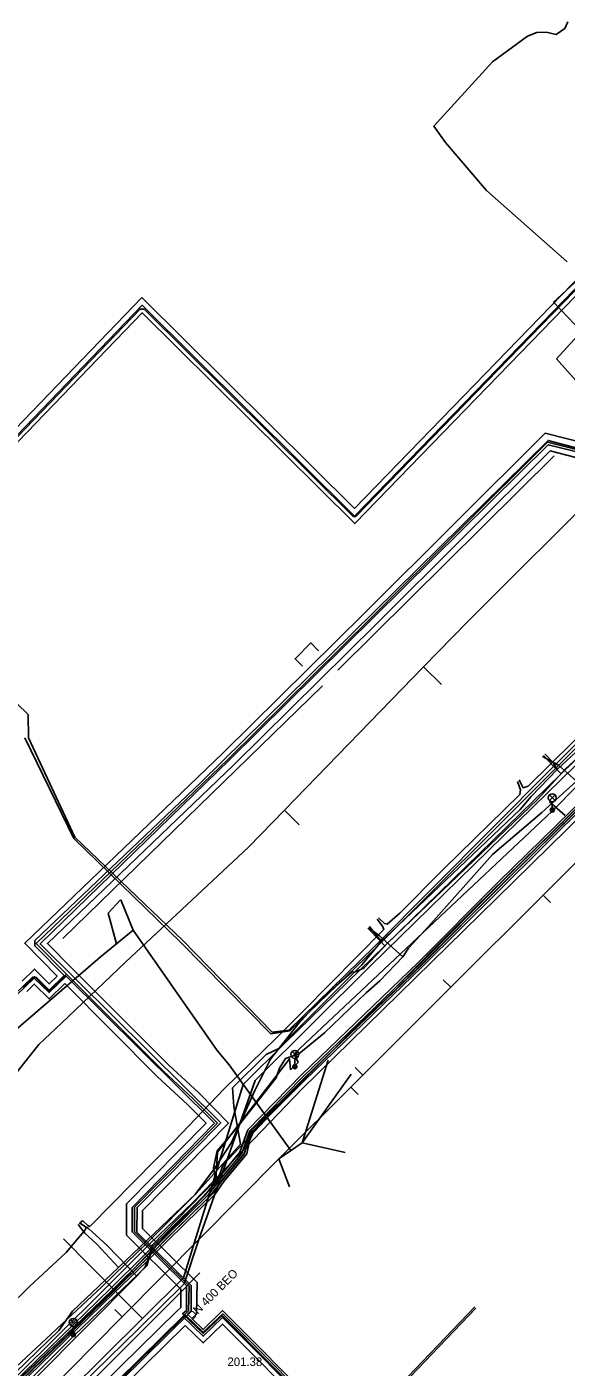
# Model space of a CAD drawing. Extents: x -598932 to -598196, y -1162210 to -1161504.
# Drawn here: x -598778.2 to -598727.6, y -1161725.1 to -1161599.2 of the extents above; entities that cross this region are included whole.
import ezdxf

# ---------------------------------------------------------------- set-up
doc = ezdxf.new("R2010")
doc.units = 0
for name, color, linetype in [('Vrstva 1', 7, 'Continuous'), ('Vrstva 12', 7, 'Continuous'), ('Vrstva 13', 7, 'Continuous'), ('Vrstva 14', 7, 'Continuous'), ('Vrstva 16', 7, 'Continuous'), ('Vrstva 25', 7, 'Continuous'), ('Vrstva 26', 7, 'Continuous'), ('Vrstva 29', 7, 'Continuous'), ('Vrstva 30', 7, 'Continuous'), ('Vrstva 33', 7, 'Continuous'), ('Vrstva 42', 7, 'Continuous'), ('Vrstva 44', 7, 'Continuous'), ('Vrstva 55', 7, 'Continuous'), ('Vrstva 58', 7, 'Continuous'), ('Vrstva 9', 7, 'Continuous')]:
    doc.layers.add(name, color=color, linetype=linetype)

msp = doc.modelspace()

# ---------------------------------------------------------------- linework, layer by layer
at = {"layer": 'Vrstva 1'}
for p, q in [((-598769.442, -1161681.198), (-598770.611, -1161682.438)), ((-598768.26, -1161684.05), (-598769.42, -1161681.2)), ((-598769.81, -1161685.315), (-598770.611, -1161682.438)), ((-598759.23, -1161696.7), (-598753.43, -1161704.739)), ((-598749.925, -1161696.249), (-598752.364, -1161704.006)), ((-598747.77, -1161697.55), (-598752.364, -1161704.006)), ((-598754.576, -1161705.527), (-598752.364, -1161704.006))]:
    msp.add_line(p, q, dxfattribs=at)
msp.add_lwpolyline([(-598810.55, -1161722.32), (-598793.435, -1161705.545), (-598771.36, -1161686.58), (-598768.26, -1161684.05), (-598760.37, -1161695.35), (-598759.23, -1161696.7)], dxfattribs=at)
at = {"layer": 'Vrstva 12'}
for p, q in [((-598769.62, -1161715.73), (-598771.68, -1161713.52)), ((-598766.65, -1161713.48), (-598771.21, -1161718.01))]:
    msp.add_line(p, q, dxfattribs=at)
for points in [[(-598698.92, -1161646.56), (-598700.94, -1161648.54), (-598734.1, -1161681.06), (-598752.39, -1161698.96), (-598760.71, -1161707.61), (-598762.61, -1161709.6), (-598766.65, -1161713.48)], [(-598711.57, -1161652.58), (-598712.15, -1161653.12), (-598713.57, -1161654.61), (-598721.86, -1161662.87), (-598728.4, -1161668.95)], [(-598728.4, -1161668.95), (-598728.79, -1161668.3), (-598729.56, -1161667.49)], [(-598728.4, -1161668.95), (-598730.87, -1161671.49), (-598731.89, -1161672.71)], [(-598731.89, -1161672.71), (-598743.98, -1161684.2), (-598744.88, -1161685.05)], [(-598744.88, -1161685.05), (-598745.35, -1161684.58), (-598746.06, -1161683.71)], [(-598744.88, -1161685.05), (-598746.78, -1161687.3), (-598754.25, -1161694.78)], [(-598754.25, -1161694.78), (-598754.58, -1161695.14), (-598755.74, -1161695.73), (-598758.91, -1161698.86), (-598758.79, -1161700.59), (-598758.18, -1161704.13), (-598762.34, -1161708.78), (-598769.62, -1161715.73)], [(-598771.68, -1161713.52), (-598772.8, -1161712.49), (-598773.41, -1161711.67)], [(-598769.62, -1161715.73), (-598773.94, -1161719.81), (-598775.23, -1161721.64), (-598782.41, -1161728.54)], [(-598771.21, -1161718.01), (-598791.29, -1161737.92), (-598802.53, -1161750.3)]]:
    msp.add_lwpolyline(points, dxfattribs=at)
at = {"layer": 'Vrstva 13'}
for p, q in [((-598754.02, -1161672.76), (-598740.96, -1161659.32)), ((-598740.96, -1161659.32), (-598739.27, -1161660.96)), ((-598754.02, -1161672.76), (-598752.65, -1161674.16)), ((-598775, -1161692.78), (-598768.96, -1161687.06))]:
    msp.add_line(p, q, dxfattribs=at)
for points in [[(-598727.47, -1161621.26), (-598735.04, -1161614.56), (-598738.9, -1161610.08), (-598740, -1161608.53), (-598734.48, -1161602.49), (-598731.21, -1161600.08), (-598730.31, -1161599.75), (-598729.44, -1161599.71), (-598728.5, -1161599.91), (-598727.68, -1161599.37), (-598727.4, -1161598.73)], [(-598726.12, -1161627.83), (-598728.75, -1161625.05), (-598726.75, -1161623.22)], [(-598723.65, -1161641.95), (-598723.26, -1161641.56), (-598720.94, -1161638.84), (-598728.47, -1161630.37), (-598726.12, -1161627.83)], [(-598740.96, -1161659.32), (-598736.85, -1161655.09), (-598723.65, -1161641.95)], [(-598768.96, -1161687.06), (-598757.42, -1161676.26), (-598754.02, -1161672.76)], [(-598780.87, -1161699.46), (-598777.11, -1161694.78), (-598775, -1161692.78)]]:
    msp.add_lwpolyline(points, dxfattribs=at)
at = {"layer": 'Vrstva 14'}
for points in [[(-598686.91, -1161631.22), (-598694.01, -1161634.29), (-598697.172, -1161639.647), (-598708.389, -1161650.966), (-598712.797, -1161655.018), (-598729.354, -1161671.164), (-598745.923, -1161687.362), (-598756.786, -1161698.152), (-598762.049, -1161713.001)], [(-598762.049, -1161713.001), (-598763.472, -1161717.27), (-598763.576, -1161717.371)], [(-598763.576, -1161717.371), (-598767.793, -1161721.498), (-598778.78, -1161732.25), (-598780.042, -1161733.466)]]:
    msp.add_lwpolyline(points, dxfattribs=at)
at = {"layer": 'Vrstva 16'}
for points in [[(-598763.52, -1161716.69), (-598757.93, -1161698.52), (-598753.93, -1161694.6), (-598744.59, -1161685.5), (-598728.03, -1161669.37), (-598711.52, -1161653.29), (-598709.02, -1161650.84), (-598704.71, -1161655.42)], [(-598729.71, -1161667.64), (-598728.81, -1161668.57), (-598728.03, -1161669.37)], [(-598746.19, -1161683.85), (-598745.03, -1161685.05), (-598744.59, -1161685.5)], [(-598774.79, -1161713.02), (-598772.3, -1161715.56), (-598767.37, -1161720.52)], [(-598805.94, -1161758.5), (-598800, -1161752.76), (-598795.62, -1161748.68), (-598777.88, -1161730.9), (-598767.37, -1161720.52), (-598763.52, -1161716.69)]]:
    msp.add_lwpolyline(points, dxfattribs=at)
at = {"layer": 'Vrstva 25'}
for points in [[(-598719.742, -1161624.967), (-598725.795, -1161622.854), (-598747.445, -1161645.145), (-598767.42, -1161625.345), (-598779.189, -1161637.582), (-598797.456, -1161630.987), (-598803.581, -1161629.034)], [(-598720.217, -1161626.194), (-598721.89, -1161630.542), (-598724.732, -1161639.377), (-598729.308, -1161638.203), (-598745.959, -1161654.763), (-598759.316, -1161667.967), (-598777.369, -1161685.289), (-598774.502, -1161688.175)], [(-598774.502, -1161688.175), (-598776.143, -1161689.796), (-598777.535, -1161688.404), (-598778.592, -1161689.425)], [(-598774.502, -1161688.175), (-598765.435, -1161697.266), (-598762.617, -1161699.869), (-598760.341, -1161702.154), (-598768.122, -1161710.062), (-598768.122, -1161712.367), (-598763.003, -1161717.433), (-598763.044, -1161719.778), (-598763.58, -1161720.316)], [(-598763.58, -1161720.316), (-598777.802, -1161734.301), (-598795.423, -1161751.633), (-598804.628, -1161760.78), (-598810.559, -1161754.845)], [(-598763.58, -1161720.316), (-598761.671, -1161722.17), (-598759.867, -1161720.402), (-598751.073, -1161729.207), (-598742.551, -1161737.734), (-598739.148, -1161734.249)]]:
    msp.add_lwpolyline(points, dxfattribs=at)
at = {"layer": 'Vrstva 26'}
for points in [[(-598803.429, -1161628.558), (-598797.295, -1161630.514), (-598779.324, -1161637.002), (-598767.428, -1161624.632), (-598747.452, -1161644.434), (-598725.932, -1161622.276), (-598720.276, -1161624.251)], [(-598720.631, -1161625.186), (-598725.659, -1161623.431), (-598747.439, -1161645.856), (-598767.411, -1161626.057), (-598779.053, -1161638.163), (-598797.617, -1161631.461), (-598803.384, -1161629.622)], [(-598775.388, -1161688.347), (-598778.439, -1161685.276), (-598759.84, -1161667.429), (-598746.487, -1161654.231), (-598729.535, -1161637.371), (-598725.229, -1161638.475), (-598722.597, -1161630.292), (-598720.917, -1161625.924)], [(-598719.68, -1161626.887), (-598721.182, -1161630.792), (-598724.234, -1161640.279), (-598729.081, -1161639.036), (-598745.43, -1161655.296), (-598758.793, -1161668.504), (-598776.3, -1161685.302), (-598773.97, -1161687.646)], [(-598778.692, -1161688.826), (-598777.529, -1161687.702), (-598776.141, -1161689.091), (-598775.388, -1161688.347)], [(-598773.971, -1161687.645), (-598764.914, -1161696.725), (-598762.096, -1161699.328), (-598759.286, -1161702.151), (-598767.372, -1161710.369), (-598767.372, -1161712.054), (-598762.248, -1161717.126), (-598762.299, -1161720.093), (-598762.724, -1161720.52)], [(-598774.683, -1161689.056), (-598776.145, -1161690.501), (-598777.541, -1161689.105), (-598778.244, -1161689.785)], [(-598764.111, -1161719.786), (-598763.788, -1161719.463), (-598763.759, -1161717.741), (-598768.872, -1161712.68), (-598768.872, -1161709.755), (-598761.396, -1161702.157), (-598763.137, -1161700.409), (-598765.955, -1161697.806), (-598774.683, -1161689.056)], [(-598810.029, -1161754.315), (-598804.626, -1161759.721), (-598795.95, -1161751.1), (-598778.328, -1161733.766), (-598764.106, -1161719.781)], [(-598762.724, -1161720.52), (-598761.672, -1161721.541), (-598759.864, -1161719.769), (-598750.755, -1161728.889), (-598742.555, -1161737.094), (-598739.47, -1161733.934)], [(-598763.363, -1161721.154), (-598777.276, -1161734.835), (-598794.895, -1161752.166), (-598804.63, -1161761.84), (-598811.09, -1161755.376)], [(-598738.826, -1161734.563), (-598742.547, -1161738.375), (-598751.391, -1161729.525), (-598759.87, -1161721.036), (-598761.67, -1161722.798), (-598763.363, -1161721.154)]]:
    msp.add_lwpolyline(points, dxfattribs=at)
at = {"layer": 'Vrstva 29'}
for p, q in [((-598728.682, -1161639.495), (-598749.015, -1161659.609)), ((-598750.471, -1161661.103), (-598774.861, -1161684.809))]:
    msp.add_line(p, q, dxfattribs=at)
msp.add_lwpolyline([(-598750.825, -1161657.811), (-598751.57, -1161657.071), (-598753.032, -1161658.543), (-598752.338, -1161659.233)], dxfattribs=at)
at = {"layer": 'Vrstva 30'}
for points in [[(-598647.032, -1161641.137), (-598652.899, -1161625.604), (-598681.381, -1161612.847), (-598687.572, -1161615.273), (-598688.268, -1161613.528), (-598688.393, -1161613.459), (-598700.945, -1161618.33), (-598701.027, -1161618.495), (-598700.484, -1161619.895), (-598709.123, -1161623.497), (-598710.849, -1161629.048), (-598720.343, -1161626.028), (-598722.057, -1161630.434), (-598724.869, -1161639.208), (-598729.272, -1161638.045), (-598761.914, -1161670.206), (-598777.488, -1161684.996), (-598777.488, -1161685.524), (-598774.748, -1161688.292), (-598776.141, -1161689.663), (-598777.33, -1161688.489), (-598777.724, -1161688.444), (-598792.286, -1161702.439)], [(-598810.719, -1161754.936), (-598804.637, -1161761.054), (-598762.81, -1161719.841), (-598762.788, -1161717.399), (-598767.899, -1161712.396), (-598767.879, -1161710.078), (-598760.022, -1161702.127), (-598776.989, -1161685.334), (-598759.185, -1161668.036), (-598729.249, -1161638.446), (-598724.611, -1161639.58), (-598721.696, -1161630.609), (-598719.628, -1161625.122), (-598725.779, -1161622.994), (-598747.341, -1161645.193), (-598747.571, -1161645.193), (-598767.228, -1161625.719), (-598767.595, -1161625.719), (-598779.142, -1161637.747), (-598797.512, -1161631.089), (-598803.541, -1161629.179), (-598806.355, -1161636.247), (-598810.188, -1161635.203), (-598811.825, -1161639.792)], [(-598820.222, -1161744.665), (-598811.82, -1161735.679), (-598818.744, -1161728.441), (-598809.235, -1161719.225), (-598790.863, -1161701.315), (-598777.544, -1161688.533), (-598776.151, -1161689.91), (-598774.559, -1161688.361), (-598760.6, -1161702.173), (-598768.357, -1161710.094), (-598768.357, -1161712.366), (-598763.251, -1161717.417), (-598763.251, -1161719.756), (-598763.613, -1161720.068), (-598761.683, -1161721.926), (-598759.897, -1161720.244), (-598750.651, -1161729.513), (-598742.552, -1161737.617), (-598738.771, -1161733.774), (-598734.4, -1161738.092), (-598730.43, -1161738.809), (-598719.083, -1161749.96)], [(-598736.156, -1161719.415), (-598744.506, -1161728.161), (-598738.949, -1161733.59), (-598738.949, -1161733.738), (-598742.441, -1161737.306), (-598742.64, -1161737.306), (-598748.758, -1161731.159), (-598759.841, -1161720.081), (-598761.672, -1161721.799), (-598763.331, -1161720.203), (-598804.632, -1161760.913), (-598810.651, -1161754.895)], [(-598719.046, -1161749.906), (-598730.17, -1161738.978), (-598730.141, -1161738.864), (-598730.3, -1161738.708), (-598734.336, -1161737.98), (-598744.285, -1161728.164), (-598736.057, -1161719.531)]]:
    msp.add_lwpolyline(points, dxfattribs=at)
at = {"layer": 'Vrstva 33'}
for p, q in [((-598729.135, -1161671.345), (-598728.605, -1161671.875)), ((-598729.135, -1161671.875), (-598728.605, -1161671.345)), ((-598728.87, -1161672.76), (-598728.87, -1161671.985)), ((-598753.325, -1161695.445), (-598752.795, -1161695.975)), ((-598753.325, -1161695.975), (-598752.795, -1161695.445)), ((-598753.06, -1161696.86), (-598753.06, -1161696.085)), ((-598774.145, -1161720.615), (-598773.615, -1161721.145)), ((-598774.145, -1161721.145), (-598773.615, -1161720.615)), ((-598773.88, -1161722.03), (-598773.88, -1161721.255))]:
    msp.add_line(p, q, dxfattribs=at)
for centre, radius in [((-598728.87, -1161671.61), 0.375), ((-598728.87, -1161672.76), 0.19), ((-598728.87, -1161672.76), 0.05), ((-598753.06, -1161695.71), 0.375), ((-598753.06, -1161696.86), 0.19), ((-598753.06, -1161696.86), 0.05), ((-598773.88, -1161720.88), 0.375), ((-598773.88, -1161722.03), 0.19), ((-598773.88, -1161722.03), 0.05)]:
    msp.add_circle(centre, radius, dxfattribs=at)
at = {"layer": 'Vrstva 42'}
for points in [[(-598647.032, -1161641.137), (-598652.899, -1161625.604), (-598681.381, -1161612.847), (-598687.572, -1161615.273), (-598688.268, -1161613.528), (-598688.393, -1161613.459), (-598700.945, -1161618.33), (-598701.027, -1161618.495), (-598700.484, -1161619.895), (-598709.123, -1161623.497), (-598710.849, -1161629.048), (-598720.343, -1161626.028), (-598722.057, -1161630.434), (-598724.869, -1161639.208), (-598729.272, -1161638.045), (-598761.914, -1161670.206), (-598777.488, -1161684.996), (-598777.488, -1161685.524), (-598774.748, -1161688.292), (-598776.141, -1161689.663), (-598777.33, -1161688.489), (-598777.724, -1161688.444), (-598792.286, -1161702.439)], [(-598810.719, -1161754.936), (-598804.637, -1161761.054), (-598762.81, -1161719.841), (-598762.788, -1161717.399), (-598767.899, -1161712.396), (-598767.879, -1161710.078), (-598760.022, -1161702.127), (-598776.989, -1161685.334), (-598759.185, -1161668.036), (-598729.249, -1161638.446), (-598724.611, -1161639.58), (-598721.696, -1161630.609), (-598719.628, -1161625.122), (-598725.779, -1161622.994), (-598747.341, -1161645.193), (-598747.571, -1161645.193), (-598767.228, -1161625.719), (-598767.595, -1161625.719), (-598779.142, -1161637.747), (-598797.512, -1161631.089), (-598803.541, -1161629.179), (-598806.355, -1161636.247), (-598810.188, -1161635.203), (-598811.825, -1161639.792)], [(-598731.972, -1161669.911), (-598731.62, -1161670.67), (-598731.15, -1161670.51), (-598724.94, -1161664.4), (-598721.37, -1161661.16), (-598717.88, -1161657.67), (-598714.27, -1161654.23), (-598711.45, -1161651.36), (-598709.67, -1161649.41), (-598709.61, -1161649.26), (-598709.71, -1161649), (-598710.157, -1161648.461)], [(-598745.191, -1161682.883), (-598744.64, -1161683.4), (-598744.38, -1161683.47), (-598743.21, -1161682.43), (-598739.1, -1161678.31), (-598731.92, -1161671.31), (-598731.86, -1161670.86), (-598732.15, -1161670.086)], [(-598784.25, -1161723.64), (-598777.99, -1161717.52), (-598774.55, -1161714.3), (-598772.72, -1161712.15), (-598772.7, -1161712), (-598773.172, -1161711.567), (-598773.143, -1161711.401), (-598772.977, -1161711.346), (-598772.517, -1161711.775), (-598772.31, -1161711.86), (-598766.19, -1161705.63), (-598764.36, -1161703.82), (-598759.69, -1161698.95), (-598754.79, -1161694.15), (-598752.3, -1161691.67), (-598744.7, -1161683.97), (-598744.84, -1161683.67), (-598745.328, -1161683.019)], [(-598820.222, -1161744.665), (-598811.82, -1161735.679), (-598818.744, -1161728.441), (-598809.235, -1161719.225), (-598790.863, -1161701.315), (-598777.544, -1161688.533), (-598776.151, -1161689.91), (-598774.559, -1161688.361), (-598760.6, -1161702.173), (-598768.357, -1161710.094), (-598768.357, -1161712.366), (-598763.251, -1161717.417), (-598763.251, -1161719.756), (-598763.613, -1161720.068), (-598761.683, -1161721.926), (-598759.897, -1161720.244), (-598750.651, -1161729.513), (-598742.552, -1161737.617), (-598738.771, -1161733.774), (-598734.4, -1161738.092), (-598730.43, -1161738.809), (-598719.083, -1161749.96)], [(-598736.156, -1161719.415), (-598744.506, -1161728.161), (-598738.949, -1161733.59), (-598738.949, -1161733.738), (-598742.441, -1161737.306), (-598742.64, -1161737.306), (-598748.758, -1161731.159), (-598759.841, -1161720.081), (-598761.672, -1161721.799), (-598763.331, -1161720.203), (-598804.632, -1161760.913), (-598810.651, -1161754.895)], [(-598719.046, -1161749.906), (-598730.17, -1161738.978), (-598730.141, -1161738.864), (-598730.3, -1161738.708), (-598734.336, -1161737.98), (-598744.285, -1161728.164), (-598736.057, -1161719.531)]]:
    msp.add_lwpolyline(points, dxfattribs=at)
at = {"layer": 'Vrstva 44'}
for points in [[(-598687.319, -1161626.808), (-598686.741, -1161628.69), (-598687.951, -1161629.003), (-598690.993, -1161630.175), (-598694.503, -1161631.528), (-598700.322, -1161634.301), (-598700.591, -1161634.43), (-598701.975, -1161635.089), (-598701.153, -1161638.507), (-598701.06, -1161638.893), (-598700.915, -1161639.495), (-598701.289, -1161639.657), (-598701.529, -1161639.761), (-598702.47, -1161640.168), (-598703.843, -1161644.12), (-598728.858, -1161669.153), (-598745.511, -1161685.764), (-598753.539, -1161693.49), (-598755.309, -1161693.781), (-598763.788, -1161685.207), (-598773.836, -1161675.437), (-598778.424, -1161665.98)], [(-598800.682, -1161641.912), (-598778.126, -1161663.798), (-598778.08, -1161665.978), (-598773.724, -1161675.314), (-598763.585, -1161685.018), (-598755.197, -1161693.608), (-598753.619, -1161693.434), (-598745.605, -1161685.605), (-598729.031, -1161668.938), (-598703.99, -1161643.975), (-598702.711, -1161640.094), (-598701.456, -1161639.52), (-598701.215, -1161639.409), (-598701.115, -1161639.364), (-598701.152, -1161639.202), (-598701.243, -1161638.808), (-598702.139, -1161634.906), (-598700.754, -1161634.233), (-598700.541, -1161634.129), (-598694.546, -1161631.214), (-598690.993, -1161630.175), (-598687.821, -1161629.248), (-598686.511, -1161628.893), (-598685.399, -1161629.972)], [(-598780.563, -1161728.042), (-598770.209, -1161717.988), (-598767.1, -1161715.029), (-598765.11, -1161713.009), (-598760.727, -1161708.746), (-598759.9, -1161707.52), (-598757.753, -1161704.945), (-598757.516, -1161703.76), (-598757.124, -1161702.843), (-598752.29, -1161698.029), (-598741.24, -1161687.349), (-598734.04, -1161680.219), (-598725.58, -1161671.819), (-598709.44, -1161655.908), (-598707.221, -1161653.8), (-598706.621, -1161653.159), (-598705.462, -1161652.081), (-598705.002, -1161651.54), (-598704.027, -1161650.674), (-598703.75, -1161649.767), (-598703.779, -1161648.886), (-598704.437, -1161647.65), (-598704.541, -1161646.665)], [(-598780.417, -1161728.178), (-598770.071, -1161718.132), (-598766.96, -1161715.171), (-598764.97, -1161713.151), (-598760.573, -1161708.874), (-598759.74, -1161707.64), (-598757.567, -1161705.035), (-598757.324, -1161703.82), (-598756.956, -1161702.957), (-598752.15, -1161698.171), (-598741.1, -1161687.491), (-598733.9, -1161680.361), (-598725.44, -1161671.961), (-598709.3, -1161656.052), (-598707.079, -1161653.94), (-598706.479, -1161653.301), (-598705.318, -1161652.219), (-598704.858, -1161651.68), (-598703.853, -1161650.786), (-598703.55, -1161649.793), (-598703.581, -1161648.834), (-598704.243, -1161647.59), (-598704.34, -1161646.676)]]:
    msp.add_lwpolyline(points, dxfattribs=at)
at = {"layer": 'Vrstva 55'}
for points in [[(-598752.75, -1161696.47), (-598753.11, -1161695.67), (-598728.88, -1161672.85), (-598719.42, -1161663.3), (-598709.18, -1161653.24)], [(-598798.79, -1161747), (-598773.75, -1161722.08), (-598766.93, -1161715.53), (-598766.48, -1161713.62), (-598760.48, -1161707.49), (-598760.34, -1161704.89), (-598753.57, -1161696.12), (-598753.47, -1161697.17)], [(-598753.47, -1161697.17), (-598753.11, -1161696.82), (-598752.75, -1161696.47)]]:
    msp.add_lwpolyline(points, dxfattribs=at)
at = {"layer": 'Vrstva 58'}
msp.add_line((-598727.66, -1161673.28), (-598729.15, -1161671.98), dxfattribs=at)
for points in [[(-598709.89, -1161655.98), (-598710.83, -1161656.95), (-598718.26, -1161664.31), (-598727.24, -1161673.25), (-598736.15, -1161681.94), (-598745.23, -1161691.04), (-598752.52, -1161698.38), (-598752.88, -1161698.72), (-598759.81, -1161706.09), (-598760.38, -1161707.72), (-598765.21, -1161712.71), (-598767.68, -1161715.31), (-598769.3, -1161717), (-598773.03, -1161720.59), (-598779.68, -1161726.88), (-598787.1, -1161734.11), (-598794.69, -1161741.52), (-598801.25, -1161748.5), (-598812.82, -1161758.59), (-598813.89, -1161758.68), (-598815.57, -1161757.946)], [(-598721.61, -1161663.37), (-598727.63, -1161668.88), (-598730.23, -1161671.74), (-598737.74, -1161678.95), (-598744.28, -1161685.2), (-598746.59, -1161687.62), (-598747.4, -1161687.96), (-598747.71, -1161688), (-598749.19, -1161689.27), (-598750.82, -1161690.75), (-598752.77, -1161692.9), (-598755.34, -1161696.17), (-598756.86, -1161699.16), (-598759.01, -1161703.97), (-598760.6, -1161706.42), (-598762.42, -1161708.85), (-598766.78, -1161713.24), (-598771.2, -1161717.54), (-598780.19, -1161725.93)], [(-598726.61, -1161670.05), (-598728.3, -1161668.54), (-598729.791, -1161667.723)], [(-598726.61, -1161670.05), (-598729.21, -1161672.41), (-598729.87, -1161672.98), (-598734.48, -1161676.93), (-598740.54, -1161683.74), (-598742.37, -1161685.73), (-598742.91, -1161686.54)], [(-598780.813, -1161727.79), (-598770.41, -1161717.727), (-598767.311, -1161714.668), (-598765.261, -1161712.618), (-598761.33, -1161708.717), (-598760.236, -1161707.324), (-598758.217, -1161704.899), (-598757.464, -1161702.781), (-598752.391, -1161697.608), (-598741.46, -1161687.077), (-598733.911, -1161679.508), (-598725.83, -1161671.587)], [(-598780.67, -1161727.93), (-598770.27, -1161717.87), (-598767.17, -1161714.81), (-598765.12, -1161712.76), (-598761.18, -1161708.85), (-598760.08, -1161707.45), (-598758.04, -1161705), (-598757.29, -1161702.89), (-598752.25, -1161697.75), (-598741.32, -1161687.22), (-598733.77, -1161679.65), (-598725.69, -1161671.73)], [(-598780.527, -1161728.07), (-598770.13, -1161718.013), (-598767.029, -1161714.952), (-598764.979, -1161712.902), (-598761.03, -1161708.983), (-598759.924, -1161707.576), (-598757.863, -1161705.101), (-598757.116, -1161702.999), (-598752.109, -1161697.892), (-598741.18, -1161687.363), (-598733.629, -1161679.792), (-598725.55, -1161671.873)], [(-598780.527, -1161728.07), (-598770.13, -1161718.013), (-598767.029, -1161714.952), (-598764.979, -1161712.902), (-598761.03, -1161708.983), (-598759.924, -1161707.576), (-598757.863, -1161705.101), (-598757.116, -1161702.999), (-598752.109, -1161697.892), (-598741.18, -1161687.363), (-598733.629, -1161679.792), (-598725.55, -1161671.873)], [(-598742.91, -1161686.54), (-598745.15, -1161684.54), (-598746.148, -1161683.821)], [(-598742.91, -1161686.54), (-598745.08, -1161688.8), (-598746.35, -1161689.92), (-598750.27, -1161693.68), (-598752.69, -1161695.65), (-598753.95, -1161696.08), (-598754.51, -1161697.01), (-598754.82, -1161697.91), (-598758.63, -1161702.77), (-598760.37, -1161704.77), (-598760.7, -1161706.36), (-598760.47, -1161707.63), (-598761.59, -1161709.03), (-598766.45, -1161714.04), (-598767.12, -1161715.67), (-598767.91, -1161716.54)], [(-598767.91, -1161716.54), (-598770.7, -1161713.66), (-598772.46, -1161712.06), (-598773.31, -1161711.52)], [(-598767.91, -1161716.54), (-598777.5, -1161726.18), (-598781.8, -1161730.36)]]:
    msp.add_lwpolyline(points, dxfattribs=at)
at = {"layer": 'Vrstva 9'}
for p, q in [((-598729.032, -1161681.457), (-598729.738, -1161680.749)), ((-598739.117, -1161688.692), (-598738.41, -1161689.4)), ((-598747.386, -1161696.941), (-598746.68, -1161697.649)), ((-598747.106, -1161699.487), (-598747.812, -1161698.779)), ((-598752.364, -1161704.006), (-598754.577, -1161705.527)), ((-598748.335, -1161704.928), (-598752.364, -1161704.006)), ((-598753.553, -1161708.14), (-598754.577, -1161705.527)), ((-598761.975, -1161716.231), (-598764.099, -1161718.349)), ((-598764.099, -1161718.349), (-598814.706, -1161768.957)), ((-598769.983, -1161719.656), (-598769.273, -1161720.36))]:
    msp.add_line(p, q, dxfattribs=at)
for points in [[(-598720.35, -1161671.384), (-598721.624, -1161672.655), (-598721.957, -1161672.987), (-598722.219, -1161673.248), (-598729.738, -1161680.749), (-598738.41, -1161689.4), (-598746.68, -1161697.649), (-598747.812, -1161698.779), (-598754.354, -1161705.305), (-598754.577, -1161705.527)], [(-598754.577, -1161705.527), (-598769.273, -1161720.36), (-598776.831, -1161727.99), (-598777.5, -1161728.664), (-598783.329, -1161734.672)]]:
    msp.add_lwpolyline(points, dxfattribs=at)

# ---------------------------------------------------------------- texts
at = {"layer": 'Vrstva 12'}
msp.add_text('DN 400 BEO', height=0.8, rotation=45, dxfattribs=at).set_placement((-598762.71, -1161720.718))
msp.add_text('201.38', height=0.8, dxfattribs=at).set_placement((-598759.394, -1161724.972))

doc.saveas('drawing.dxf')
